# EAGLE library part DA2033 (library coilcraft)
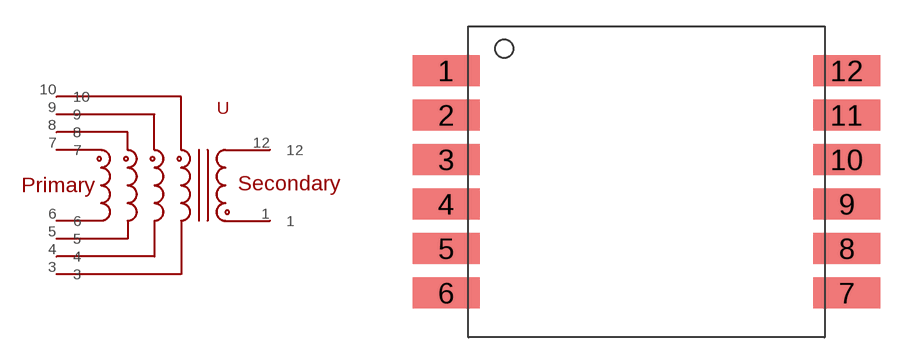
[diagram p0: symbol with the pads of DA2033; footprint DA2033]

Designator prefix -

## DA2033  [DA2033]
1  1
3  3
4  4
5  5
6  6
7  7
8  8
9  9
10  10
12  12

## Footprint DA2033 (pad centres in mm)
smd 3.81 x 1.778: 1 -11.43,6.35; 2 -11.43,3.81; 3 -11.43,1.27; 4 -11.43,-1.27; 5 -11.43,-3.81; 6 -11.43,-6.35; 7 11.43,-6.35; 8 11.43,-3.81; 9 11.43,-1.27; 10 11.43,1.27; 11 11.43,3.81; 12 11.43,6.35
